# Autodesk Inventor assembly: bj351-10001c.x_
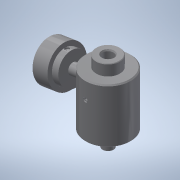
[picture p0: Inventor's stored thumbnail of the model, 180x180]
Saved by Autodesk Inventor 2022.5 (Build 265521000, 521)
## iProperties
Part Number: bj351-10001c.x_
Material: 一般
Document SubType Name: Assembly
Designer: ImaoCorp
Sending System: SOLIDWORKS 2017-2017317
MC: AMD64
MC_MODEL: Intel64 Family 6 Model 60 Stepping 3, GenuineIntel
OS: Windows_NT
FRU: Parasolid Version 29.0, build 201,  4-17-2017
FORMAT: text
GUISE: transmit
KEY: bj351-10001c
FILE: bj351-10001c.x_t
DATE: Fri Mar 15 10:12:34 2019
Author: ImaoCorp
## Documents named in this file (4)
- X:\14_SW2022-Inv2022\00_全2023-1023新製品(TCC)まで\b\bj351-10001c\BJ351-10001C.iam
- X:\14_SW2022-Inv2022\00_全2023-1023新製品(TCC)まで\b\bj351-10001c\bj351-10001c_01.ipt
- X:\14_SW2022-Inv2022\00_全2023-1023新製品(TCC)まで\b\bj351-10001c\bj351-10001c_02.ipt
- X:\14_SW2022-Inv2022\00_全2023-1023新製品(TCC)まで\b\bj351-10001c\bj351-10001c_03.ipt
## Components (3 placed, 3 different names)
1. bj351-10001c_01
2. bj351-10001c_02
3. bj351-10001c_03
